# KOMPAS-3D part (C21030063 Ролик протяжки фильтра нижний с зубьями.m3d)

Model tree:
1. Плоскость XY
2. Плоскость ZX
3. Плоскость ZY
4. Ось X
5. Ось Y
6. Ось Z
7. Начало координат
8. Эскиз:1
9. Внеш. контур, ступень 1: Шестерня Z=46
     Толщина стенки 1 = 1; Толщина стенки 2 = 1; Расстояние 1 = 10; Расстояние 2 = 5; На расстояние 2 = 5
10. Внеш. контур, ступень 1: Шестерня Z=46, фаска слева
     Угол = 45; Длина 1 = 0.5; Длина 2 = 0.5
11. Внеш. контур, ступень 1: Шестерня Z=46, фаска справа
     Угол = 45; Длина 1 = 0.5; Длина 2 = 0.5
12. Эскиз:2
13. Внеш. контур, ступень 1: Шестерня Z=46, профиль зуба
     Толщина стенки 1 = 1; Толщина стенки 2 = 1; Расстояние 2 = 10; Расстояние 1 = 5; На расстояние 1 = 5
14. Ось операции:1
15. Внеш. контур, ступень 1: Шестерня Z=46, зубья  (with: Внеш. контур, ступень 1: Шестерня Z=46, профиль зуба)  (labels: Экземпляр ( 1, 1 );; Экземпляр ( 1, 2 );; Экземпляр ( 1, 3 );; Экземпляр ( 1, 4 );)
     N 1 = 1; Шаг 1 = 1; N 2 = 46; Шаг 2 = 7.82609
16. Эскиз:3
17. Внеш. контур, ступень 2: Цилиндр. D=40
     Толщина стенки 1 = 1; Толщина стенки 2 = 1; Расстояние 1 = 3; На расстояние 1 = 3; Расстояние 2 = 10
18. Эскиз:4
19. Внеш. контур, ступень 3: Цилиндр. D=46,35
     Толщина стенки 1 = 1; Толщина стенки 2 = 1; Расстояние 1 = 5; На расстояние 1 = 5; Расстояние 2 = 10
20. Эскиз:5
21. Внеш. контур, ступень 4: Цилиндр. D=30
     Толщина стенки 1 = 1; Толщина стенки 2 = 1; Расстояние 1 = 13; На расстояние 1 = 12.5; Расстояние 2 = 10
22. Фаска:3
     Угол = 45; Длина 1 = 0.5; Длина 2 = 0.5
23. Эскиз:6
24. Внутр. контур, ступень 1: Цилиндр. D=15
     Толщина стенки 1 = 1; Толщина стенки 2 = 1; Расстояние 2 = 10; Расстояние 1 = 26; На расстояние 1 = 25.5
25. Фаска:4
     Угол = 45; Длина 1 = 0.5; Длина 2 = 0.5
26. Фаска:5
     Угол = 45; Длина 1 = 0.5; Длина 2 = 0.5
27. Скругление:1  (labels: Полуось 2)
     Радиус = 0.5
28. Скругление:2  (labels: Полуось 2)
     Радиус = 0.5
29. Скругление:3  (labels: Полуось 2)
     Радиус = 0.5
30. Эскиз:7
31. Вырезать элемент выдавливания:1
     Расстояние 2 = 24; Расстояние 1 = 26; На расстояние 1 = 25.5
32. Условное изображение резьбы:1
     Длина резьбы = 8; Шаг резьбы = 1; Номинальный диаметр резьбы = 6.00003
33. Фаска:6
     Угол = 45; Длина 1 = 1; Длина 2 = 1

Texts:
  Ролик протяжки фильтра нижний с зубьями
  3D модуль программы "Shaft+" (Аскон-Курган)
  Сталь ХВГ  ГОСТ 5950-2000
  125 1 126 1 127 1 128 0 50 1|SPDS|125 1 126 1 127 1 128 0 50 1
  129 1 130 1 131 1 132 0 50 1|SPDS|129 1 130 1 131 1 132 0 50 1
  Экземпляр ( 1, 1 );
  Экземпляр ( 1, 2 );
  Экземпляр ( 1, 3 );
  Экземпляр ( 1, 4 );
  Экземпляр ( 1, 5 );
  Экземпляр ( 1, 6 );
  Экземпляр ( 1, 7 );
  Экземпляр ( 1, 8 );
  Экземпляр ( 1, 9 );
  Экземпляр ( 1, 10 );
  Экземпляр ( 1, 11 );
  Экземпляр ( 1, 12 );
  Экземпляр ( 1, 13 );
  Экземпляр ( 1, 14 );
  Экземпляр ( 1, 15 );
  Экземпляр ( 1, 16 );
  Экземпляр ( 1, 17 );
  Экземпляр ( 1, 18 );
  Экземпляр ( 1, 19 );
  Экземпляр ( 1, 20 );
  Экземпляр ( 1, 21 );
  Экземпляр ( 1, 22 );
  Экземпляр ( 1, 23 );
  Экземпляр ( 1, 24 );
  Экземпляр ( 1, 25 );
  Экземпляр ( 1, 26 );
  Экземпляр ( 1, 27 );
  Экземпляр ( 1, 28 );
  Экземпляр ( 1, 29 );
  Экземпляр ( 1, 30 );
  Экземпляр ( 1, 31 );
  Экземпляр ( 1, 32 );
  Экземпляр ( 1, 33 );
  Экземпляр ( 1, 34 );
  Экземпляр ( 1, 35 );
  Экземпляр ( 1, 36 );
  Экземпляр ( 1, 37 );
  Экземпляр ( 1, 38 );
  Экземпляр ( 1, 39 );
  Экземпляр ( 1, 40 );
  Экземпляр ( 1, 41 );
  Экземпляр ( 1, 42 );
  Экземпляр ( 1, 43 );
  Экземпляр ( 1, 44 );
  Экземпляр ( 1, 45 );
  Экземпляр ( 1, 46 );
  Номер 1
  Номер 2
  Полуось 2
